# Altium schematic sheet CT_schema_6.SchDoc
size 411 x 401 mm
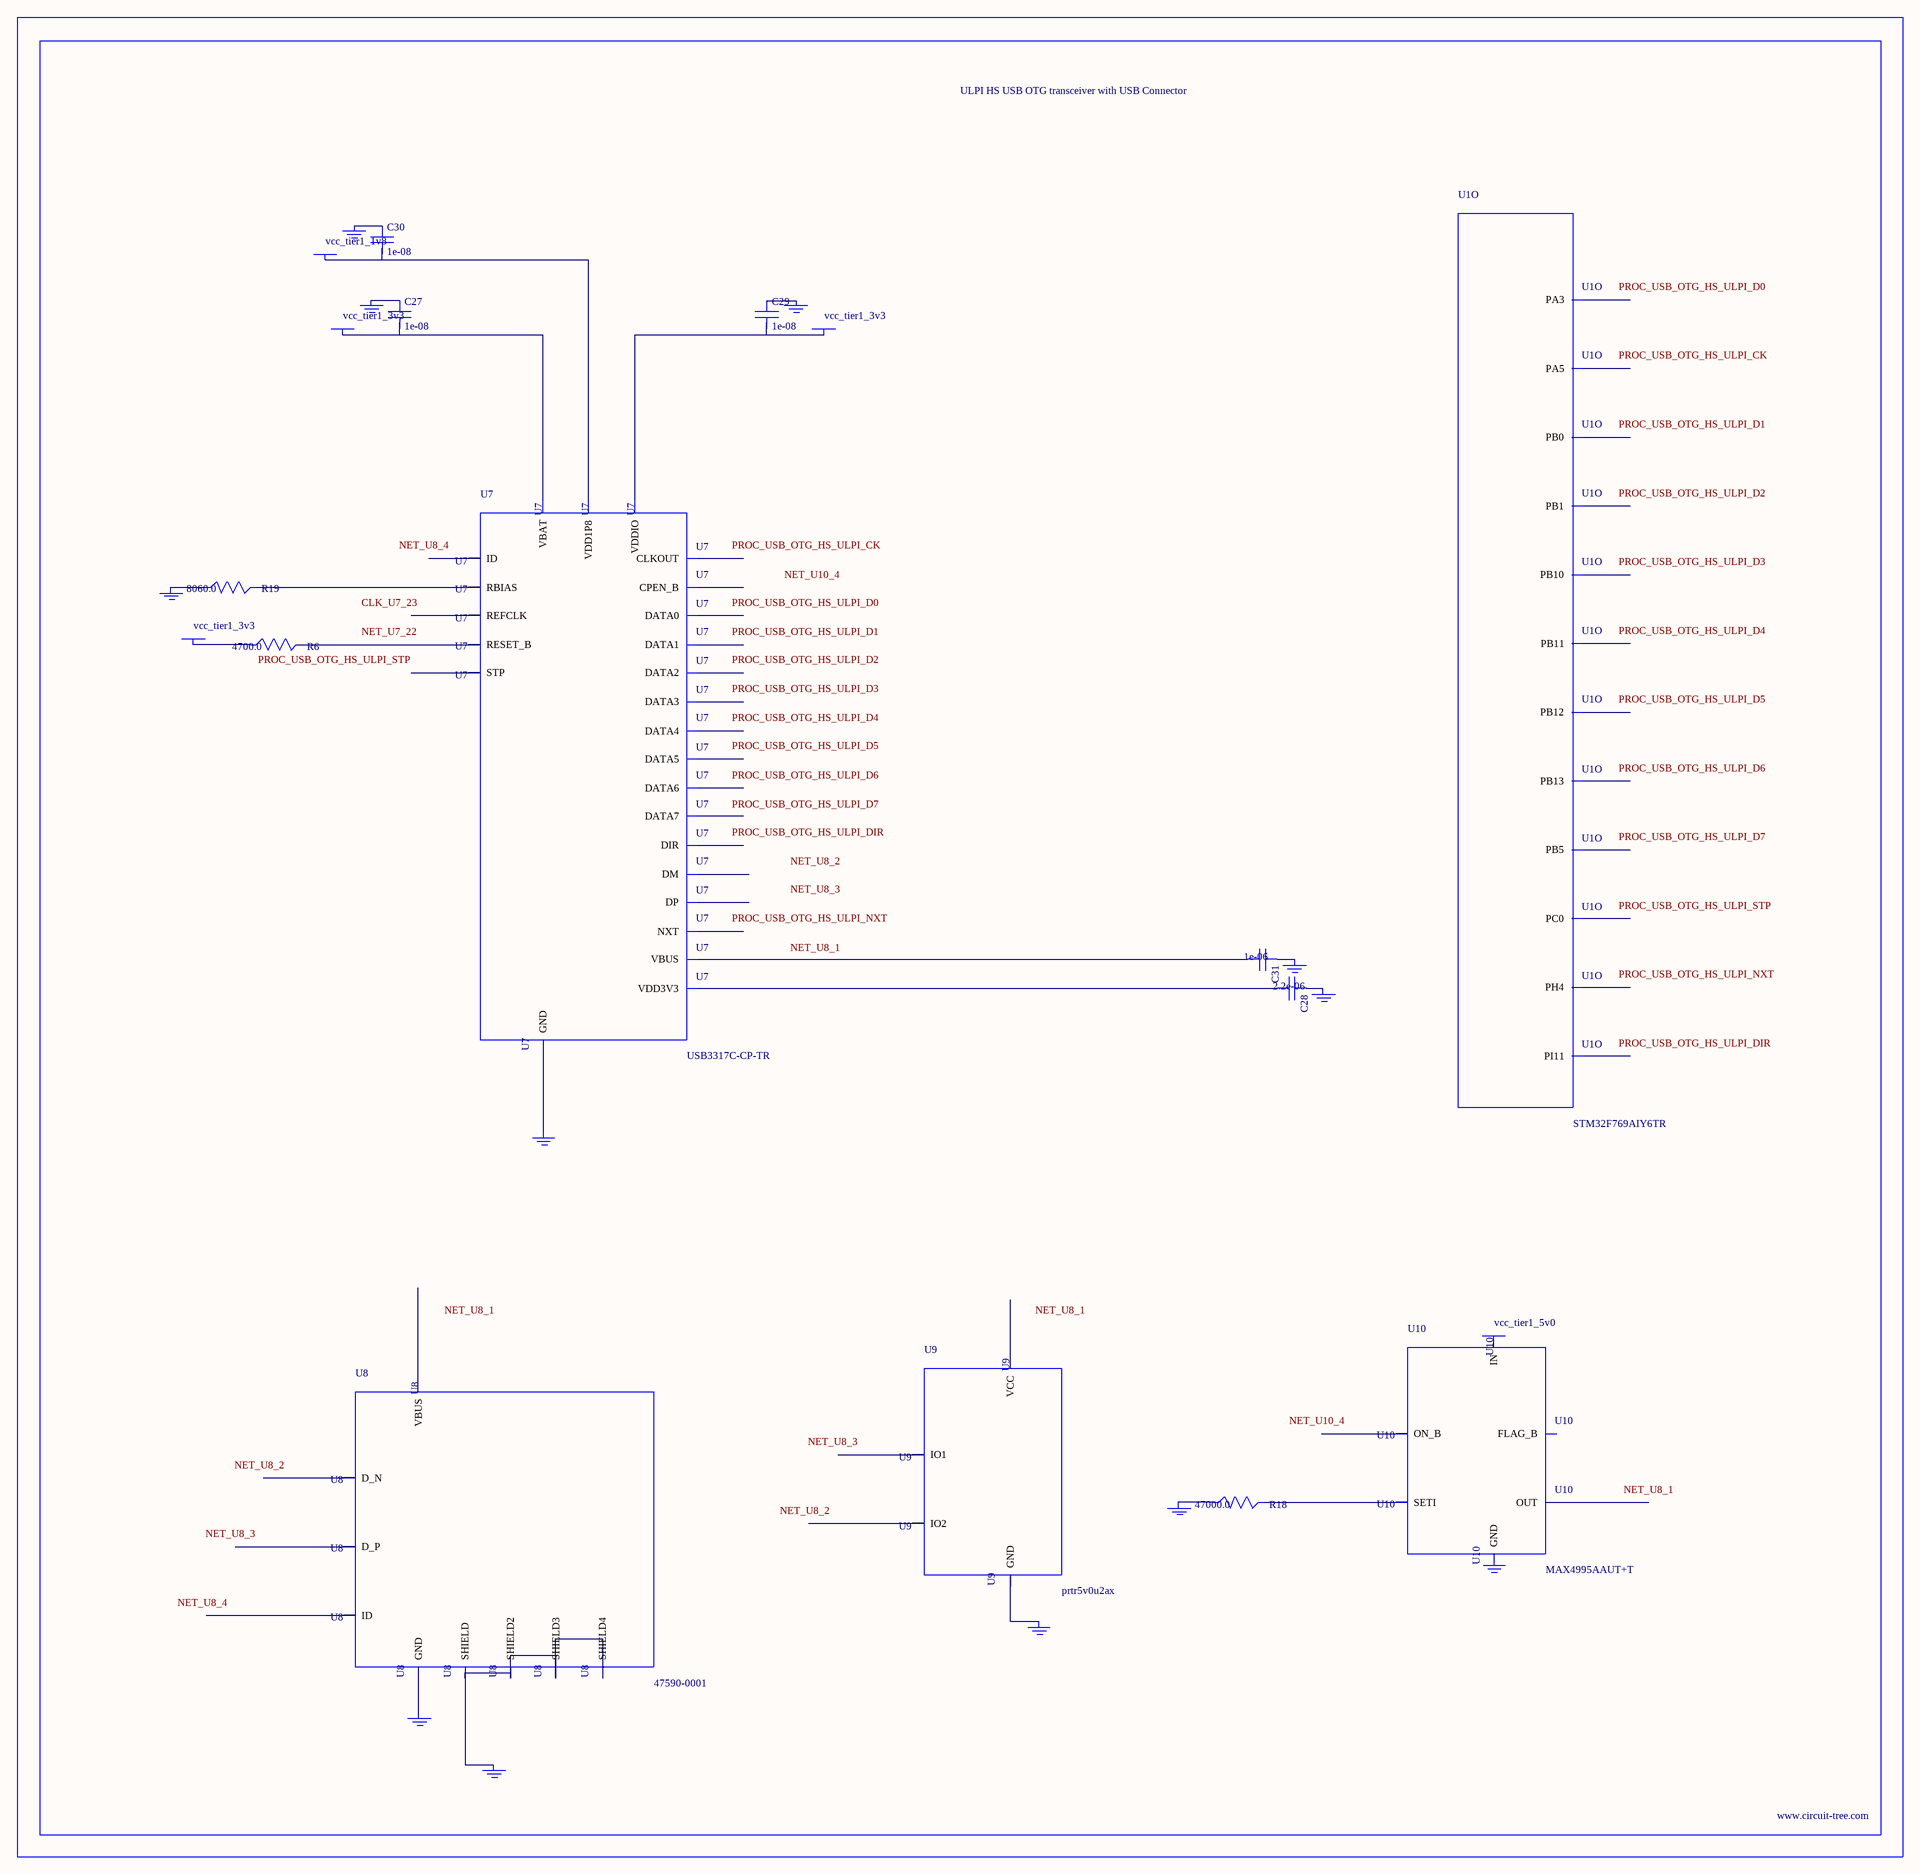
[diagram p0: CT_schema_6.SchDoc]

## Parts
BORDER5  (no value)
C27  1e-08  [C0402]
C28  2.2e-06  [C0603]
C29  1e-08  [C0402]
C30  1e-08  [C0402]
C31  1e-06  [C0603]
GND_INSTANCE_5_0  (no value)
GND_INSTANCE_5_1  (no value)
GND_INSTANCE_5_2  (no value)
GND_INSTANCE_5_3  (no value)
GND_INSTANCE_5_4  (no value)
GND_INSTANCE_5_5  (no value)
GND_INSTANCE_5_6  (no value)
GND_INSTANCE_5_7  (no value)
GND_INSTANCE_5_8  (no value)
GND_INSTANCE_5_9  (no value)
GND_INSTANCE_5_10  (no value)
GND_INSTANCE_5_11  (no value)
POWER_INSTANCE_5_0  vcc_tier1_3v3
POWER_INSTANCE_5_1  vcc_tier1_3v3
POWER_INSTANCE_5_2  vcc_tier1_1v8
POWER_INSTANCE_5_3  vcc_tier1_3v3
POWER_INSTANCE_5_4  vcc_tier1_5v0
R6  4700.0  [R0603]
R18  47000.0  [R0603]
R19  8060.0  [R0603]
U1  STM32F769AIY6TR  [WLCSP180]  (part O of 15)
U7  USB3317C-CP-TR  [QFN-24]
U8  47590-0001  [MICRO_USB_AB]
U9  prtr5v0u2ax  [SOT143B]
U10  MAX4995AAUT+T  [SOT-23-6]

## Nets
NetC27_1: C27.1 GND_INSTANCE_5_1.0(GND)
NetC27_2: C27.2 POWER_INSTANCE_5_0.0(PWR) U7.3(VBAT)
NetC28_1: C28.1 GND_INSTANCE_5_2.0(GND)
NetC28_2: C28.2 U7.4(VDD3V3)
NetC29_1: C29.1 GND_INSTANCE_5_3.0(GND)
NetC29_2: C29.2 POWER_INSTANCE_5_1.0(PWR) U7.17(VDDIO)
NetC30_1: C30.1 GND_INSTANCE_5_4.0(GND)
NetC30_2: C30.2 POWER_INSTANCE_5_2.0(PWR) U7.21(VDD1P8)
NetC31_1: C31.1 GND_INSTANCE_5_0.0(GND)
NetC31_2: C31.2 U7.2(VBUS)
NetGND_INSTANCE_5_5_0: GND_INSTANCE_5_5.0(GND) R19.1
NetGND_INSTANCE_5_6_0: GND_INSTANCE_5_6.0(GND) U7.25(GND)
NetGND_INSTANCE_5_7_0: GND_INSTANCE_5_7.0(GND) U8.6(SHIELD) U8.7(SHIELD2) U8.8(SHIELD3) U8.9(SHIELD4)
NetGND_INSTANCE_5_8_0: GND_INSTANCE_5_8.0(GND) U8.5(GND)
NetGND_INSTANCE_5_9_0: GND_INSTANCE_5_9.0(GND) U9.1(GND)
NetGND_INSTANCE_5_10_0: GND_INSTANCE_5_10.0(GND) R18.1
NetPOWER_INSTANCE_5_3_0: POWER_INSTANCE_5_3.0(PWR) R6.1
NetR6_2: R6.2 U7.22(RESET_B)
NetR18_2: R18.2 U10.3(SETI)
NetR19_2: R19.2 U7.24(RBIAS)

Not connected (* = marked no-connect by the designer): GND_INSTANCE_5_11 0(GND); POWER_INSTANCE_5_4 0(PWR); U1 A9(PB5) F11(PI11) H8(PB12) J5(PB13) J8(PB1) K5(PB10) L5(PB11) L12(PC0) M10(PA3) N12(PH4) P10(PB0) P11(PA5); U7 1(ID) 5(DM) 6(DP) 7(CPEN_B) 8(DATA7) 9(DATA6) 10(DATA5) 11(DATA4) 12(CLKOUT) 13(DATA3) 14(DATA2) 15(DATA1) 16(DATA0) 18(NXT) 19(DIR) 20(STP) 23(REFCLK); U8 1(VBUS) 2(D_N) 3(D_P) 4(ID); U9 2(IO1) 3(IO2) 4(VCC); U10 1(OUT) 2(GND) 4(ON_B) 5(IN) 6(FLAG_B)

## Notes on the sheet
- Labels drawn without touching a wire or pin: CLK_U7_23, NET_U7_22, NET_U8_1, NET_U8_2, NET_U8_3, NET_U8_4, NET_U10_4, PROC_USB_OTG_HS_ULPI_CK, PROC_USB_OTG_HS_ULPI_D0, PROC_USB_OTG_HS_ULPI_D1, PROC_USB_OTG_HS_ULPI_D2, PROC_USB_OTG_HS_ULPI_D3, PROC_USB_OTG_HS_ULPI_D4, PROC_USB_OTG_HS_ULPI_D5, PROC_USB_OTG_HS_ULPI_D6, PROC_USB_OTG_HS_ULPI_D7, PROC_USB_OTG_HS_ULPI_DIR, PROC_USB_OTG_HS_ULPI_NXT, PROC_USB_OTG_HS_ULPI_STP

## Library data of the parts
BORDER5 = BORDER_PAGE5
C27 C29 C30 = C0402C103K3RAC
C28 = C0603C225K8RACTU
C31 = C0603C105K3RACTU
GND_INSTANCE_5_0-GND_INSTANCE_5_11 = GND
POWER_INSTANCE_5_0-POWER_INSTANCE_5_4 = PWR
R6 = RC0603JR-074K7L
R18 = RC0603JR-0747KL
R19 = ERJ-3EKF8061V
